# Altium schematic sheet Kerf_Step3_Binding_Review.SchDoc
size A; SheetNumber: 1; SheetTotal: 1
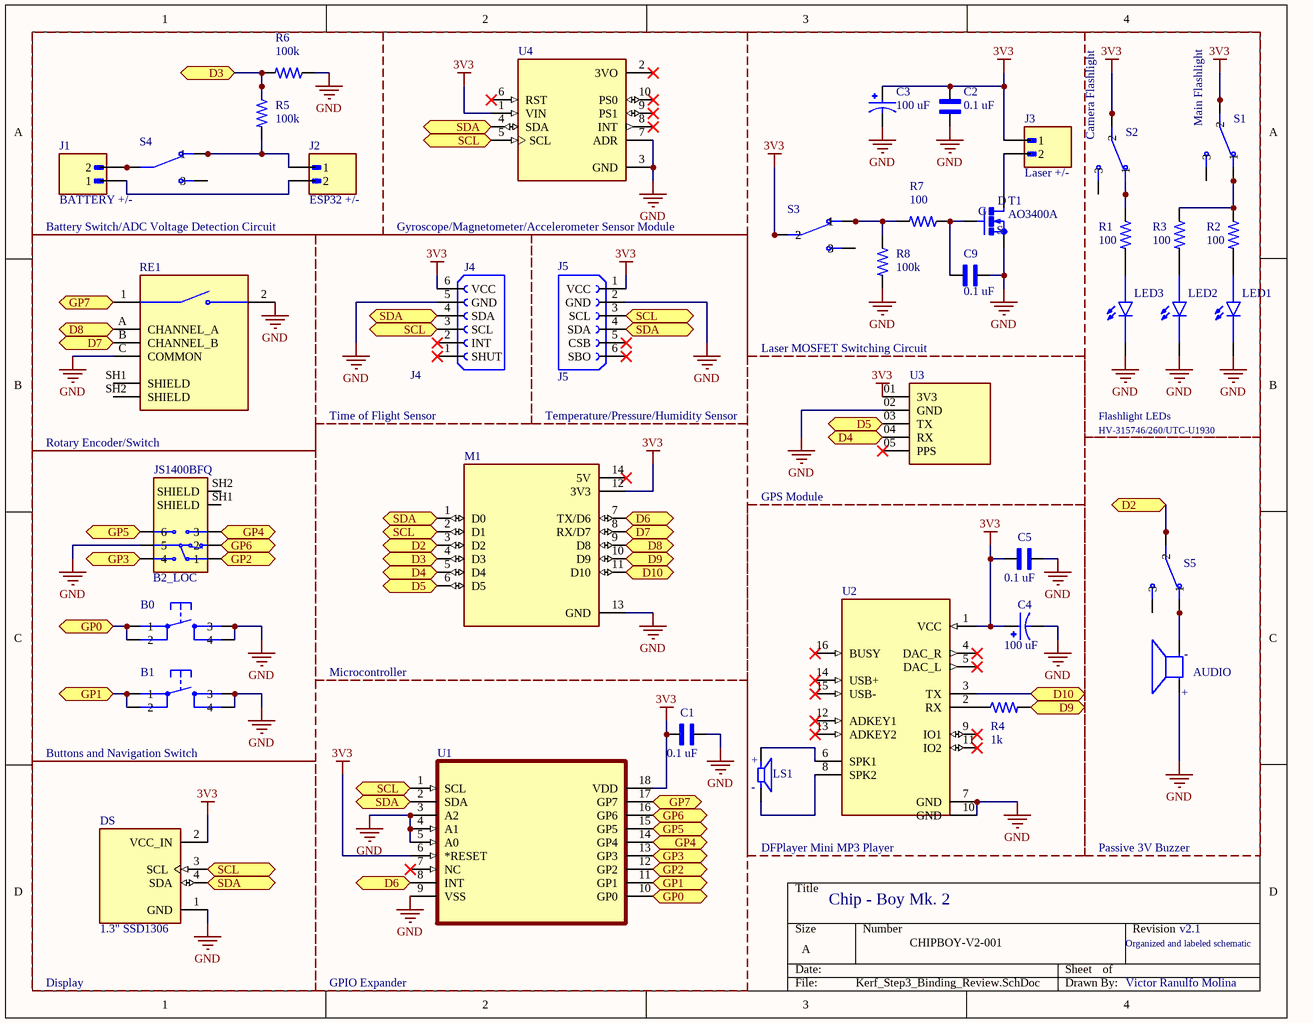
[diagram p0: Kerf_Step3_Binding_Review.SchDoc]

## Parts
AUDIO  (no value)  [Kerf_AUDIO_original]
B0  SKHHANA010  [Kerf_B0_original]  (value not drawn)
B1  SKHHANA010  [Kerf_B1_original]  (value not drawn)
B2_LOC  JS1400BFQ  [Kerf_B2_LOC_original]
C1  0.1 uF  [Kerf_C1_original]
C2  0.1 uF  [Kerf_C2_original]
C3  100 uF  [Kerf_C3_original]
C4  100 uF  [Kerf_C4_original]
C5  0.1 uF  [Kerf_C5_original]
C9  0.1 uF  [Kerf_C9_original]
DS  1.3" SSD1306  [Kerf_DS_original]
J1  BATTERY +/-  [Kerf_J1_original]
J2  ESP32 +/-  [Kerf_J2_original]
J3  Laser +/-  [Kerf_J3_original]
J4  J4  [Kerf_J4_original]
J5  J5  [Kerf_J5_original]
LED1  led_through_hole  [Kerf_LED1_original]  (value not drawn)
LED2  led_through_hole  [Kerf_LED2_original]  (value not drawn)
LED3  led_through_hole  [Kerf_LED3_original]  (value not drawn)
LS1  15mm speaker  [Kerf_LS1_original]  (value not drawn)
M1  (no value)  [Kerf_M1_original]
R1  100  [Kerf_R1_original]
R2  100  [Kerf_R2_original]
R3  100  [Kerf_R3_original]
R4  1k  [Kerf_R4_original]
R5  100k  [Kerf_R5_original]
R6  100k  [Kerf_R6_original]
R7  100  [Kerf_R7_original]
R8  100k  [Kerf_R8_original]
RE1  rotary encoder  [Kerf_RE1_original]  (value not drawn)
S1  Main Flashlight  [Kerf_S1_original]
S2  Camera Flashlight  [Kerf_S2_original]
S3  switch top actuated  [Kerf_S3_original]  (value not drawn)
S4  switch top actuated  [Kerf_S4_original]  (value not drawn)
S5  switch top actuated  [Kerf_S5_original]  (value not drawn)
T1  AO3400A  [Kerf_T1_original]
U1  gpio extender  [Kerf_U1_original]  (value not drawn)
U2  DFPLAYER  [Kerf_U2_original]  (value not drawn)
U3  ATGM336H  [Kerf_U3_original]  (value not drawn)
U4  BNO055  [Kerf_U4_original]  (value not drawn)

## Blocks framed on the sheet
Battery Switch/ADC Voltage Detection Circuit: J1 J2 R5 R6 S4
Gyroscope/Magnetometer/Accelerometer Sensor Module: U4
Laser MOSFET Switching Circuit: C2 C3 C9 J3 R7 R8 S3 T1
Flashlight LEDs: LED1-LED3 R1-R3 S1 S2
Temperature/Pressure/Humidity Sensor: J5
Passive 3V Buzzer: AUDIO S5

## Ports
D2 (bidir, see CHIPBOY_Mk_II[2C]), D2 (bidir, see CHIPBOY_Mk_II[4B]), D3 (bidir, see CHIPBOY_Mk_II[1A]), D3 (bidir, see CHIPBOY_Mk_II[2C]), D4 (bidir, see CHIPBOY_Mk_II[2C]), D4 (bidir, see CHIPBOY_Mk_II[3B]), D5 (bidir, see CHIPBOY_Mk_II[2C]), D5 (bidir, see CHIPBOY_Mk_II[3B]), D6 (bidir, see CHIPBOY_Mk_II[2C]), D6 (bidir, see CHIPBOY_Mk_II[2D]), D7 (bidir, see CHIPBOY_Mk_II[1B]), D7 (bidir, see CHIPBOY_Mk_II[2C]), D8 (bidir, see CHIPBOY_Mk_II[1B]), D8 (bidir, see CHIPBOY_Mk_II[2C]), D9 (bidir, see CHIPBOY_Mk_II[2C]), D9 (bidir, see CHIPBOY_Mk_II[4C]), D10 (bidir, see CHIPBOY_Mk_II[2C]), D10 (bidir, see CHIPBOY_Mk_II[4C]), GP0 (bidir, see CHIPBOY_Mk_II[1C]), GP0 (bidir, see CHIPBOY_Mk_II[3D]), GP1 (bidir, see CHIPBOY_Mk_II[1C]), GP1 (bidir, see CHIPBOY_Mk_II[3D]), GP2 (bidir, see CHIPBOY_Mk_II[1C]), GP2 (bidir, see CHIPBOY_Mk_II[3D]), GP3 (bidir, see CHIPBOY_Mk_II[1C]), GP3 (bidir, see CHIPBOY_Mk_II[3D]), GP4 (bidir, see CHIPBOY_Mk_II[1C]), GP4 (bidir, see CHIPBOY_Mk_II[3D]), GP5 (bidir, see CHIPBOY_Mk_II[1C]), GP5 (bidir, see CHIPBOY_Mk_II[3D]), GP6 (bidir, see CHIPBOY_Mk_II[1C]), GP6 (bidir, see CHIPBOY_Mk_II[3D]), GP7 (bidir, see CHIPBOY_Mk_II[1B]), GP7 (bidir, see CHIPBOY_Mk_II[3D]), SCL (bidir, see CHIPBOY_Mk_II[1D], CHIPBOY_Mk_II[2A], CHIPBOY_Mk_II[2B], CHIPBOY_Mk_II[2C]), SCL (bidir, see CHIPBOY_Mk_II[1D], CHIPBOY_Mk_II[2A], CHIPBOY_Mk_II[2B], CHIPBOY_Mk_II[2C], CHIPBOY_Mk_II[2D]), SCL (bidir, see CHIPBOY_Mk_II[1D], CHIPBOY_Mk_II[2A], CHIPBOY_Mk_II[2B], CHIPBOY_Mk_II[2D]), SCL (bidir, see CHIPBOY_Mk_II[1D], CHIPBOY_Mk_II[2B], CHIPBOY_Mk_II[2C], CHIPBOY_Mk_II[2D]), SCL (bidir, see CHIPBOY_Mk_II[2A], CHIPBOY_Mk_II[2B], CHIPBOY_Mk_II[2C], CHIPBOY_Mk_II[2D]), SDA (bidir, see CHIPBOY_Mk_II[1D], CHIPBOY_Mk_II[2A], CHIPBOY_Mk_II[2B], CHIPBOY_Mk_II[2C]), SDA (bidir, see CHIPBOY_Mk_II[1D], CHIPBOY_Mk_II[2A], CHIPBOY_Mk_II[2B], CHIPBOY_Mk_II[2C], CHIPBOY_Mk_II[2D]), SDA (bidir, see CHIPBOY_Mk_II[1D], CHIPBOY_Mk_II[2A], CHIPBOY_Mk_II[2B], CHIPBOY_Mk_II[2D]), SDA (bidir, see CHIPBOY_Mk_II[1D], CHIPBOY_Mk_II[2B], CHIPBOY_Mk_II[2C], CHIPBOY_Mk_II[2D]), SDA (bidir, see CHIPBOY_Mk_II[2A], CHIPBOY_Mk_II[2B], CHIPBOY_Mk_II[2C], CHIPBOY_Mk_II[2D])

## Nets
3V3: C1.1 C2.1 C3.1 C4.1 C5.1 DS.2(VCC_IN) J3.1 J4.6(VCC) J5.1(VCC) M1.12(3V3) S1.3(2) S1.4 S2.3(2) S2.4 S3.3(2) S3.4(2) U1.6(*RESET) U1.18(VDD) U2.1(VCC) U3.01(3V3) U4.1(VIN)
GND: AUDIO.P B0.3 B0.4 B1.3 B1.4 B2_LOC.5 C1.2 C2.2 C3.2 C4.2 C5.2 C9.1 DS.1(GND) J4.5(GND) J5.2(GND) LED1.C LED2.C LED3.C M1.13(GND) R6.1 R8.2 RE1.2 RE1.C(COMMON) T1.2(S) U1.3(A2) U1.4(A1) U1.5(A0) U1.9(VSS) U2.7(GND) U2.10(GND) U3.02(GND) U4.3(GND) U4.7(ADR)
D2: M1.3(D2) S5.3(2) S5.4 ; port D2
D3: M1.4(D3) R5.1 R6.2 ; port D3
D4: M1.5(D4) U3.04(RX) ; port D4
D5: M1.6(D5) U3.03(TX) ; port D5
D6: M1.7(TX/D6) U1.8(INT) ; port D6
D7: M1.8(RX/D7) RE1.B(CHANNEL_B) ; port D7
D8: M1.9(D8) RE1.A(CHANNEL_A) ; port D8
D9: M1.10(D9) R4.2 ; port D9
D10: M1.11(D10) U2.3(TX) ; port D10
GP0: B0.1 B0.2 U1.10(GP0) ; port GP0
GP1: B1.1 B1.2 U1.11(GP1) ; port GP1
GP2: B2_LOC.1 U1.12(GP2) ; port GP2
GP3: B2_LOC.4 U1.13(GP3) ; port GP3
GP4: B2_LOC.3 U1.14(GP4) ; port GP4
GP5: B2_LOC.6 U1.15(GP5) ; port GP5
GP6: B2_LOC.2 U1.16(GP6) ; port GP6
GP7: RE1.1 U1.17(GP7) ; port GP7
SCL: DS.3(SCL) J4.3(SCL) J5.3(SCL) M1.2(D1) U1.1(SCL) U4.5(SCL) ; port SCL
SDA: DS.4(SDA) J4.4(SDA) J5.4(SDA) M1.1(D0) U1.2(SDA) U4.4(SDA) ; port SDA
NetAUDIO_N: AUDIO.N S5.1 S5.2
NetC9_2: C9.2 R7.1 T1.1(G)
NetJ1_1: J1.1 J2.2
NetJ1_2: J1.2 S4.3 S4.4
NetJ2_1: J2.1 R5.2 S4.1 S4.2
NetJ3_2: J3.2 T1.3(D)
NetLED1_A: LED1.A R2.2
NetLED2_A: LED2.A R3.2
NetLED3_A: LED3.A R1.2
NetLS1_1: LS1.1(P) U2.6(SPK1)
NetLS1_2: LS1.2(M) U2.8(SPK2)
NetR1_1: R1.1 S2.1 S2.2
NetR2_1: R2.1 R3.1 S1.1 S1.2
NetR4_1: R4.1 U2.2(RX)
NetR7_2: R7.2 R8.1 S3.1 S3.2(1)
NetS1_5: S1.5(3) S1.6
NetS2_5: S2.5(3) S2.6
NetS3_5: S3.5(3) S3.6(3)
NetS4_5: S4.5(3) S4.6
NetS5_5: S5.5(3) S5.6

Not connected (* = marked no-connect by the designer): B2_LOC SH1(SHIELD) SH2(SHIELD); J4 1(SHUT)* 2(INT)*; J5 5(CSB)* 6(SBO)*; M1 14(5V)*; RE1 SH1(SHIELD) SH2(SHIELD); U1 7(NC)*; U2 4(DAC_R)* 5(DAC_L)* 9(IO1)* 11(IO2)* 12(ADKEY1)* 13(ADKEY2)* 14(USB+)* 15(USB-)* 16(BUSY)*; U3 05(PPS)*; U4 2(3VO)* 6(RST)* 8(INT)* 9(PS1)* 10(PS0)*

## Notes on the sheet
- Time of Flight Sensor
- HV-315746/260/UTC-U1930
- Rotary Encoder/Switch
- GPS Module
- Microcontroller
- (near B1) Buttons and Navigation Switch
- (near U2) DFPlayer Mini MP3 Player
- Chip - Boy Mk. 2
- CHIPBOY-V2-001
- Organized and labeled schematic
- v2.1
- Display
- GPIO Expander
- Victor Ranulfo Molina

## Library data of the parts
AUDIO = Kerf_AUDIO_review_symbol
B0 = Kerf_B0_review_symbol
B1 = Kerf_B1_review_symbol
B2_LOC = Kerf_B2_LOC_review_symbol
C1 = Kerf_C1_review_symbol
C2 = Kerf_C2_review_symbol
C3 = Kerf_C3_review_symbol
C4 = Kerf_C4_review_symbol
C5 = Kerf_C5_review_symbol
C9 = Kerf_C9_review_symbol
DS = Kerf_DS_review_symbol
J1 = Kerf_J1_review_symbol
J2 = Kerf_J2_review_symbol
J3 = Kerf_J3_review_symbol
J4 = Kerf_J4_review_symbol
J5 = Kerf_J5_review_symbol
LED1 = Kerf_LED1_review_symbol
LED2 = Kerf_LED2_review_symbol
LED3 = Kerf_LED3_review_symbol
LS1 = Kerf_LS1_review_symbol
M1 = Kerf_M1_review_symbol
R1 = Kerf_R1_review_symbol
R2 = Kerf_R2_review_symbol
R3 = Kerf_R3_review_symbol
R4 = Kerf_R4_review_symbol
R5 = Kerf_R5_review_symbol
R6 = Kerf_R6_review_symbol
R7 = Kerf_R7_review_symbol
R8 = Kerf_R8_review_symbol
RE1 = Kerf_RE1_review_symbol
S1 = Kerf_S1_review_symbol
S2 = Kerf_S2_review_symbol
S3 = Kerf_S3_review_symbol
S4 = Kerf_S4_review_symbol
S5 = Kerf_S5_review_symbol
T1 = Kerf_T1_review_symbol
U1 = Kerf_U1_review_symbol
U2 = Kerf_U2_review_symbol
U3 = Kerf_U3_review_symbol
U4 = Kerf_U4_review_symbol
